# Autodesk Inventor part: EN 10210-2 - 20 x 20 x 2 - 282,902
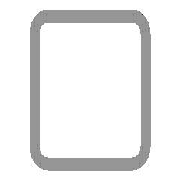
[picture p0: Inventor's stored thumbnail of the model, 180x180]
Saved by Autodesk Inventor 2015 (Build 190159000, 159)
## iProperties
_CCFamilyMember: 1
_CCFamilyDisplayName: DIN EN 10210-2 (Square) - Tube
_FrameMemberDoc: Frame Member File
_Version: 15.0.0
_GetPNFromCC: 1
Created: 2014-02
Part Number: EN 10210-2 - 20 x 20 x 2 - 282,902
Material: Steel, Mild
Description: Tube
Document SubType Name: Modeling
Standard: DIN
Designer: TREINA6
Standard Revision: 1997
Standards Organization: DIN
Language: en-US
Size Designation: 20 x 20 x 2
Categories: <MemberInstance><Categories><Category DisplayName="Structural Shapes" InternalName="089c4875-fa83-4c05-b084-43b9cc11f5ed" Mnemonic="GRDR"><CategoryParameter Dis
Stock Number: 20 x 20 x 2
Density: 7.85 g/cm^3
Appearance: Semi-Polished
IsCustomPart: 1
G_L: 282,902 mm
G_W: 20,000 mm
G_H: 20,000 mm
+AD2DC2CC-9517-46C6-A196-09C6F70E40CF+CUTDETAIL1: Miter 60,00 deg
+074C0221-DC1C-46C6-AC78-E21AE067C0E7+CUTDETAIL2: Miter 60,00 deg
Author: TREINA6
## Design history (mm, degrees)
node "Start plane"
node "End plane"
sketch "Sketch"
  geometry: L1 (-10, -7)-(-10, 7); L2 (-7, 10)-(7, 10); L3 (10, 7)-(10, -7); L4 (7, -10)-(-7, -10); L5 (-7, 8)-(7, 8); L6 (8, 7)-(8, -7); L7 (7, -8)-(-7, -8); L8 (-8, -7)-(-8, 7); L9 (0, 14.87)-(0, -14.87) reference; L10 (-14.87, 0)-(14.87, 0) reference; A1 r 3 centre (-7, -7) between (-10, -7) and (-7, -10); A2 r 3 centre (-7, 7) between (-7, 10) and (-10, 7); A3 r 3 centre (7, 7) between (10, 7) and (7, 10); A4 r 3 centre (7, -7) between (7, -10) and (10, -7); A5 r 1 centre (-7, 7) between (-7, 8) and (-8, 7); A6 r 1 centre (7, 7) between (8, 7) and (7, 8); A7 r 1 centre (7, -7) between (7, -8) and (8, -7); A8 r 1 centre (-7, -7) between (-8, -7) and (-7, -8)
  constraints: 16 end point, 16 point on circle, 8 centre point, 8 tangent, 4 parallel, 3 equal radius, 2 perpendicular, 7 other
  dimensions: "d7" = 3 radius of A1 (= G_IR); "d10" = 20 distance between parallel lines of L2 L4 (= G_H); "d11" = 20 distance between parallel lines of L1 L3 (= G_W); "d12" = 2 distance between parallel lines of L3 L6 (= G_T); "d15" = 10 distance between parallel lines of L2 L10 (= 0.5 x d10); "d16" = 10 distance between parallel lines of L9 L3 (= 0.5 x d11)
extrude "Body" new body sketch "Sketch" stored distance "d3" = 282.90163 (= G_L); taper "d4" = 0 deg
node "Driven Length"
  sketch "Sketch3"
    geometry: L1 (0, 0)-(10, 0) reference
    constraints: 2 end point, 1 horizontal
  workplane "Work Plane3"
  sketch "Sketch4"
    geometry: L1 (-2, 0)-(12, 0) reference; L2 (-2, 282.902)-(12, 282.902) reference
    dimensions: "d18" = 282.90163 distance between parallel lines of L1 L2 (derived)
workplane "Work Plane4"
split "Split1"
workplane "Work Plane5"
split "Split2"
body "Solid1"
other parameters: "G_W" = 20 [user parameter; used in 1 equation term], "G_H" = 20 [user parameter; used in 1 equation term], "G_T" = 2 [user parameter; used in 1 equation term], "G_IR" = 3 [user parameter; used in 1 equation term], "G_L" = 282.90163 (= d18) [user parameter; used in 1 equation term], "G_OFFSET_START" = 0 [user parameter; used in 1 equation term], "G_OFFSET_END" = 0 [user parameter; used in 1 equation term], "d13" = 0 (computed from G_OFFSET_START), "d14" = 282.90163 (= G_OFFSET_END + B_L), "B_L" = 282.90163 [user parameter; used in 1 equation term], "d17" = 90 deg
